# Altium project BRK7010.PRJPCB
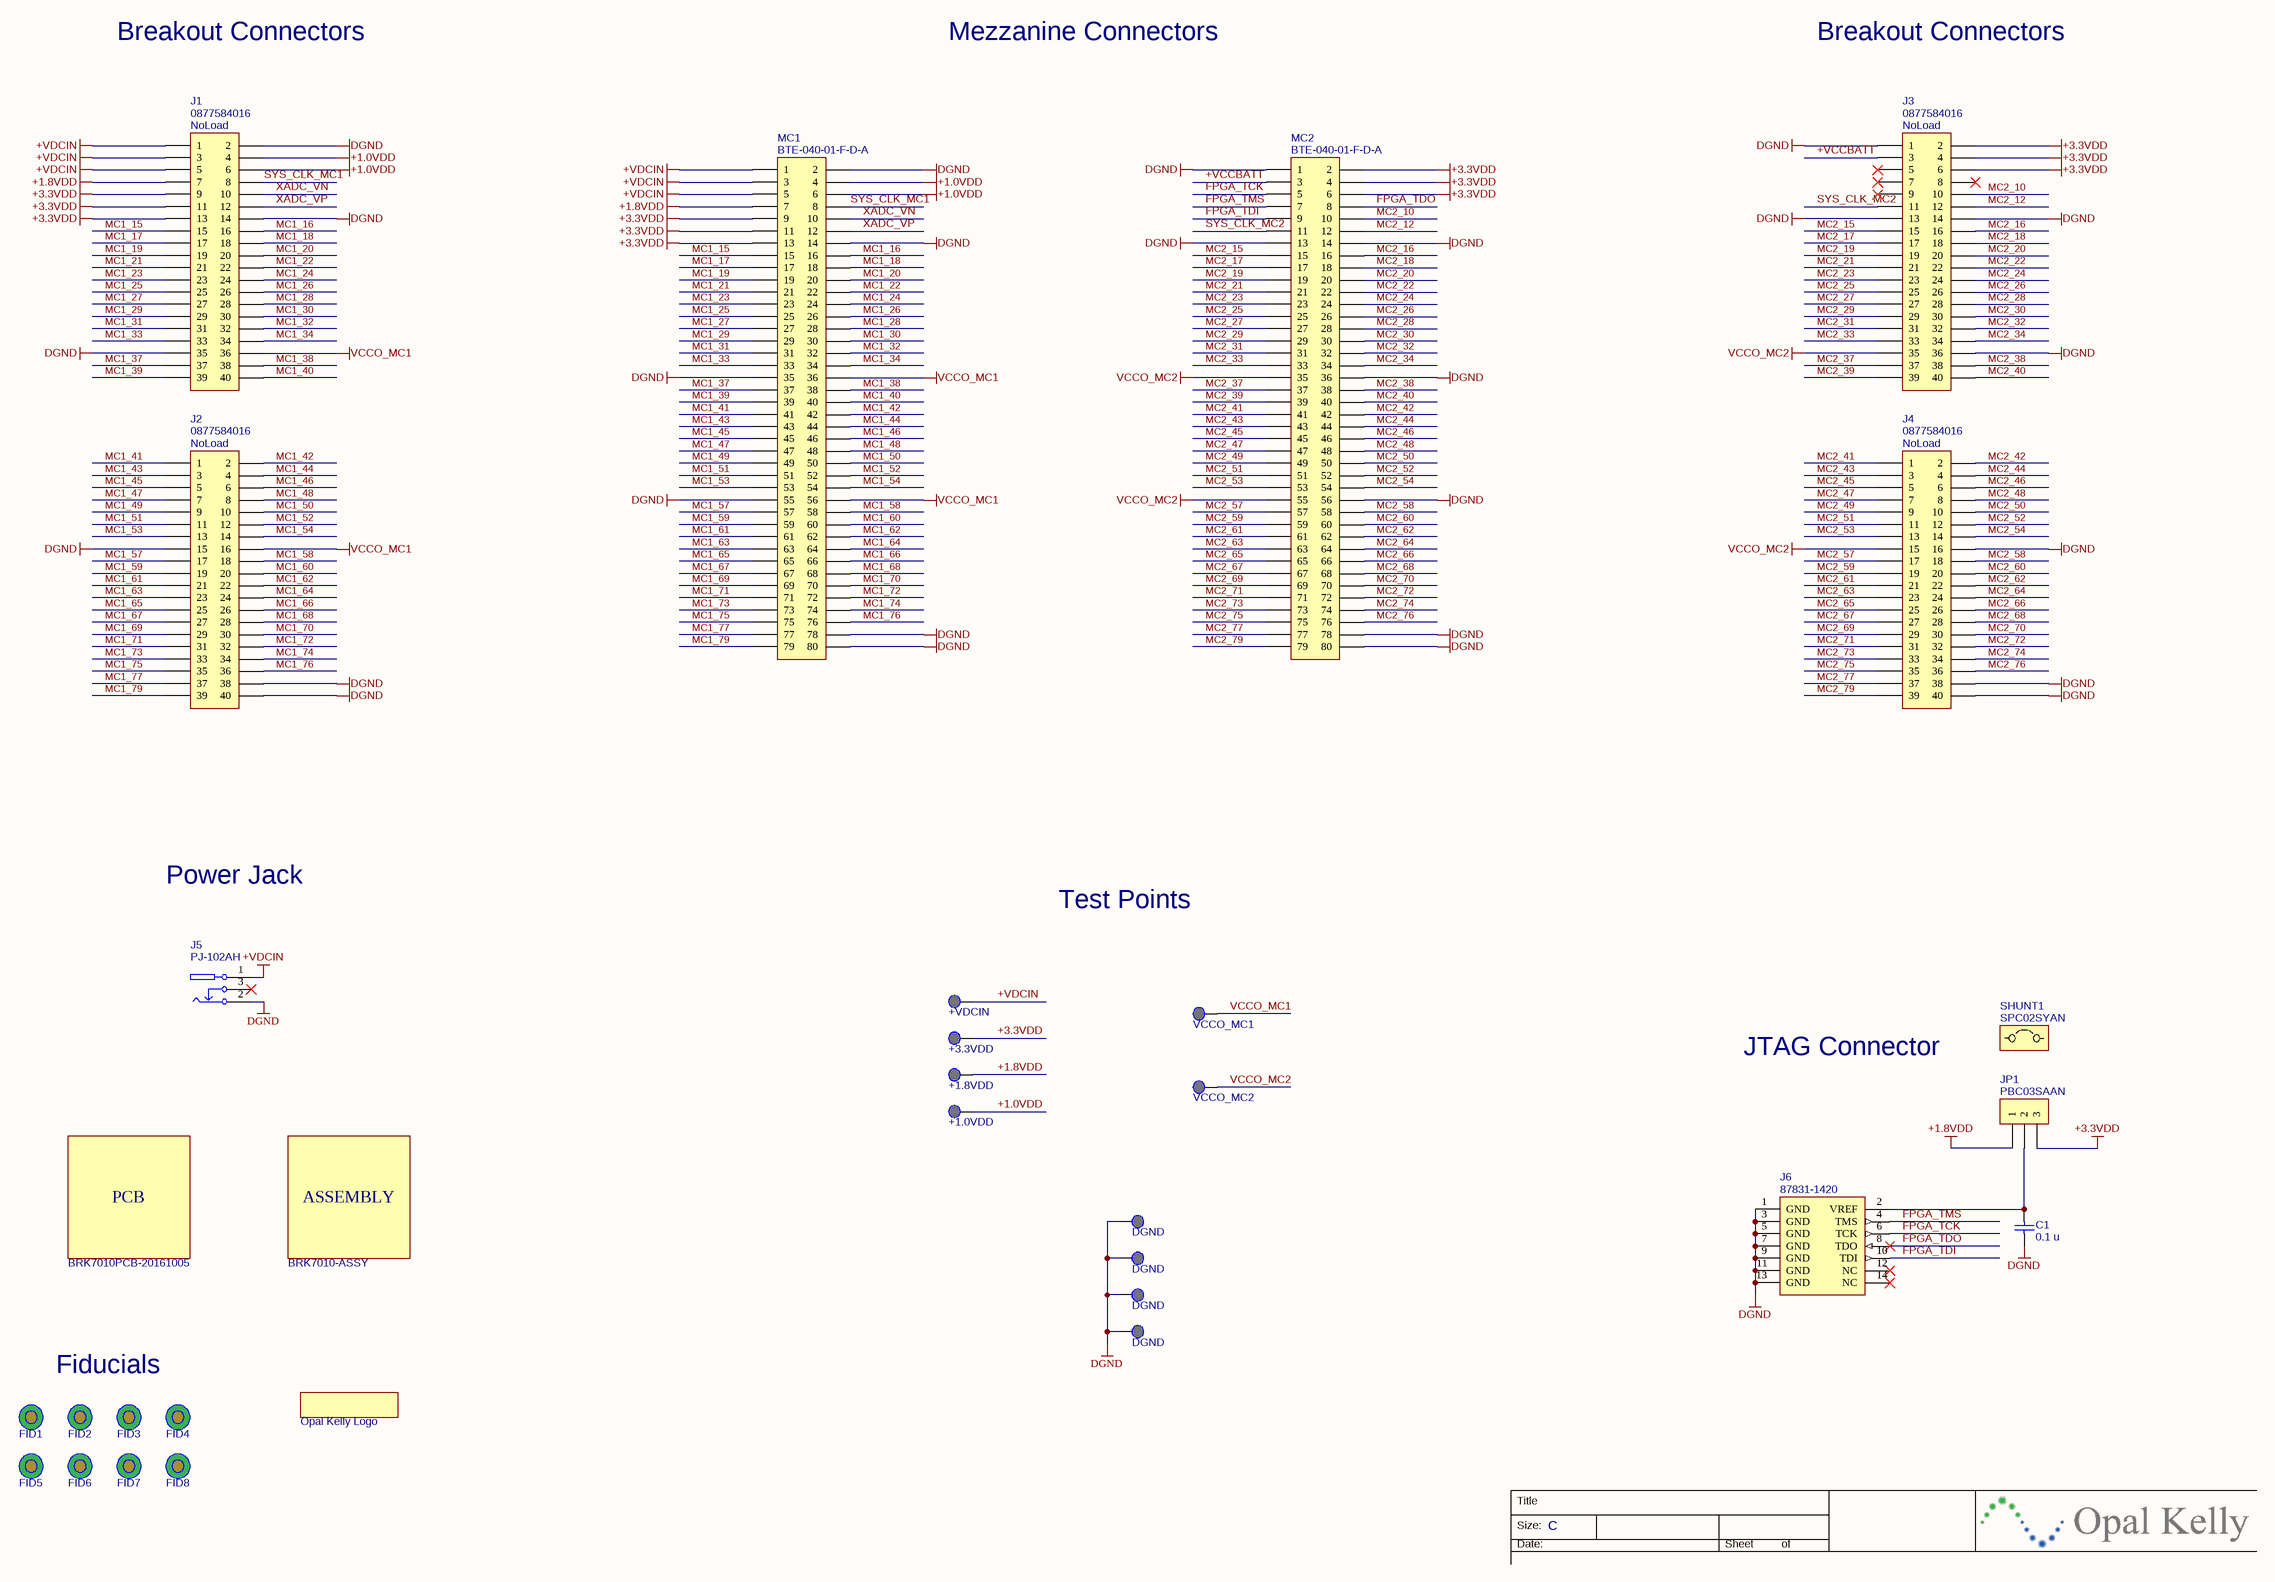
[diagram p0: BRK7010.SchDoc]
1 sheet, 32 parts. Net scope: global (net labels, ports and power ports of the same name join across sheets).
Board file: BRK7010.PcbDoc

## Sheet BRK7010.SchDoc: BRK7010
size C; Organization: Opal Kelly; Address1: 13500 SW 72nd Ave, STE 100; Address2: Portland, OR 97223; Address4: http://www.opalkelly.com; DocumentNumber: xxx; Revision: 1; SheetNumber: 1; SheetTotal: 1; PageSetup: Record=PageOptions¦CenterHorizontal=True¦CenterVertical=True¦PrintScale=0.54¦XCorrection=1.00¦YCorrection=1.00¦PrintKind=0¦BorderSize=5000000¦LeftOffset=0¦BottomOffset=0¦Orientation=2¦PaperLength=1000¦PaperWidth=1000¦Scale=100¦PaperSource=7¦PrintQuality=-4¦MediaType=1¦DitherType=10¦PaperKind=Letter¦PrintScaleMode=1

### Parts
*1  Opal Kelly Logo  [okLogo-23x5]
ASSY1  BRK7010-ASSY  (mechanical)
C1  value 0.1 u  [CAPC1608N]  (hidden comment: C0603C104K4RACTU)
FID1  FIDUCIAL  [FID1MM/2MM-SS]  (value not drawn)
FID2  FIDUCIAL  [FID1MM/2MM-SS]  (value not drawn)
FID3  FIDUCIAL  [FID1MM/2MM-SS]  (value not drawn)
FID4  FIDUCIAL  [FID1MM/2MM-SS]  (value not drawn)
FID5  FIDUCIAL  [FID1MM/2MM-SS]  (value not drawn)
FID6  FIDUCIAL  [FID1MM/2MM-SS]  (value not drawn)
FID7  FIDUCIAL  [FID1MM/2MM-SS]  (value not drawn)
FID8  FIDUCIAL  [FID1MM/2MM-SS]  (value not drawn)
J1  0877584016  [HDR2X20-2MM]
J2  0877584016  [HDR2X20-2MM]
J3  0877584016  [HDR2X20-2MM]
J4  0877584016  [HDR2X20-2MM]
J5  PJ-102AH  [CUI-PJ102A]
J6  87831-1420  [HDR2X7-2MM]
JP1  PBC03SAAN  [HDR1X3]
MC1  BTE-040-01-F-D-A  [BTE-040]
MC2  BTE-040-01-F-D-A  [BTE-040]
PCB1  BRK7010PCB-20161005  (mechanical)
SHUNT1  SPC02SYAN  (mechanical)
TP1  +VDCIN  [TP-PTH-65/100]
TP2  VCCO_MC1  [TP-PTH-65/100]
TP3  +3.3VDD  [TP-PTH-65/100]
TP4  +1.8VDD  [TP-PTH-65/100]
TP5  VCCO_MC2  [TP-PTH-65/100]
TP6  +1.0VDD  [TP-PTH-65/100]
TP7  DGND  [TP-PTH-65/100]
TP8  DGND  [TP-PTH-65/100]
TP9  DGND  [TP-PTH-65/100]
TP10  DGND  [TP-PTH-65/100]

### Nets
+1.0VDD: J1.4 J1.6 MC1.4 MC1.6 TP6.1(PIN)
+1.8VDD: J1.7 JP1.1 MC1.7 TP4.1(PIN)
+3.3VDD: J1.9 J1.11 J1.13 J3.2 J3.4 J3.6 JP1.3 MC1.9 MC1.11 MC1.13 MC2.2 MC2.4 MC2.6 TP3.1(PIN)
+VDCIN: J1.1 J1.3 J1.5 J5.1 MC1.1 MC1.3 MC1.5 TP1.1(PIN)
DGND: C1.1 J1.2 J1.14 J1.35 J2.15 J2.38 J2.40 J3.1 J3.13 J3.14 J3.36 J4.16 J4.38 J4.40 J5.2 J6.1(GND) J6.3(GND) J6.5(GND) J6.7(GND) J6.9(GND) J6.11(GND) J6.13(GND) MC1.2 MC1.14 MC1.35 MC1.55 MC1.78 MC1.80 MC2.1 MC2.13 MC2.14 MC2.36 MC2.56 MC2.78 MC2.80 TP7.1(PIN) TP8.1(PIN) TP9.1(PIN) TP10.1(PIN)
VCCO_MC1: J1.36 J2.16 MC1.36 MC1.56 TP2.1(PIN)
VCCO_MC2: J3.35 J4.15 MC2.35 MC2.55 TP5.1(PIN)
+VCCBATT: J3.3 MC2.3
FPGA_TCK: J6.6(TCK) MC2.5
FPGA_TDI: J6.10(TDI) MC2.9
FPGA_TDO: J6.8(TDO) MC2.8
FPGA_TMS: J6.4(TMS) MC2.7
MC1_15: J1.15 MC1.15
MC1_16: J1.16 MC1.16
MC1_17: J1.17 MC1.17
MC1_18: J1.18 MC1.18
MC1_19: J1.19 MC1.19
MC1_20: J1.20 MC1.20
MC1_21: J1.21 MC1.21
MC1_22: J1.22 MC1.22
MC1_23: J1.23 MC1.23
MC1_24: J1.24 MC1.24
MC1_25: J1.25 MC1.25
MC1_26: J1.26 MC1.26
MC1_27: J1.27 MC1.27
MC1_28: J1.28 MC1.28
MC1_29: J1.29 MC1.29
MC1_30: J1.30 MC1.30
MC1_31: J1.31 MC1.31
MC1_32: J1.32 MC1.32
MC1_33: J1.33 MC1.33
MC1_34: J1.34 MC1.34
MC1_37: J1.37 MC1.37
MC1_38: J1.38 MC1.38
MC1_39: J1.39 MC1.39
MC1_40: J1.40 MC1.40
MC1_41: J2.1 MC1.41
MC1_42: J2.2 MC1.42
MC1_43: J2.3 MC1.43
MC1_44: J2.4 MC1.44
MC1_45: J2.5 MC1.45
MC1_46: J2.6 MC1.46
MC1_47: J2.7 MC1.47
MC1_48: J2.8 MC1.48
MC1_49: J2.9 MC1.49
MC1_50: J2.10 MC1.50
MC1_51: J2.11 MC1.51
MC1_52: J2.12 MC1.52
MC1_53: J2.13 MC1.53
MC1_54: J2.14 MC1.54
MC1_57: J2.17 MC1.57
MC1_58: J2.18 MC1.58
MC1_59: J2.19 MC1.59
MC1_60: J2.20 MC1.60
MC1_61: J2.21 MC1.61
MC1_62: J2.22 MC1.62
MC1_63: J2.23 MC1.63
MC1_64: J2.24 MC1.64
MC1_65: J2.25 MC1.65
MC1_66: J2.26 MC1.66
MC1_67: J2.27 MC1.67
MC1_68: J2.28 MC1.68
MC1_69: J2.29 MC1.69
MC1_70: J2.30 MC1.70
MC1_71: J2.31 MC1.71
MC1_72: J2.32 MC1.72
MC1_73: J2.33 MC1.73
MC1_74: J2.34 MC1.74
MC1_75: J2.35 MC1.75
MC1_76: J2.36 MC1.76
MC1_77: J2.37 MC1.77
MC1_79: J2.39 MC1.79
MC2_10: J3.10 MC2.10
MC2_12: J3.12 MC2.12
MC2_15: J3.15 MC2.15
MC2_16: J3.16 MC2.16
MC2_17: J3.17 MC2.17
MC2_18: J3.18 MC2.18
MC2_19: J3.19 MC2.19
MC2_20: J3.20 MC2.20
MC2_21: J3.21 MC2.21
MC2_22: J3.22 MC2.22
MC2_23: J3.23 MC2.23
MC2_24: J3.24 MC2.24
MC2_25: J3.25 MC2.25
MC2_26: J3.26 MC2.26
MC2_27: J3.27 MC2.27
MC2_28: J3.28 MC2.28
MC2_29: J3.29 MC2.29
MC2_30: J3.30 MC2.30
MC2_31: J3.31 MC2.31
MC2_32: J3.32 MC2.32
MC2_33: J3.33 MC2.33
MC2_34: J3.34 MC2.34
MC2_37: J3.37 MC2.37
MC2_38: J3.38 MC2.38
MC2_39: J3.39 MC2.39
MC2_40: J3.40 MC2.40
MC2_41: J4.1 MC2.41
MC2_42: J4.2 MC2.42
MC2_43: J4.3 MC2.43
MC2_44: J4.4 MC2.44
MC2_45: J4.5 MC2.45
MC2_46: J4.6 MC2.46
MC2_47: J4.7 MC2.47
MC2_48: J4.8 MC2.48
MC2_49: J4.9 MC2.49
MC2_50: J4.10 MC2.50
MC2_51: J4.11 MC2.51
MC2_52: J4.12 MC2.52
MC2_53: J4.13 MC2.53
MC2_54: J4.14 MC2.54
MC2_57: J4.17 MC2.57
MC2_58: J4.18 MC2.58
MC2_59: J4.19 MC2.59
MC2_60: J4.20 MC2.60
MC2_61: J4.21 MC2.61
MC2_62: J4.22 MC2.62
MC2_63: J4.23 MC2.63
MC2_64: J4.24 MC2.64
MC2_65: J4.25 MC2.65
MC2_66: J4.26 MC2.66
MC2_67: J4.27 MC2.67
MC2_68: J4.28 MC2.68
MC2_69: J4.29 MC2.69
MC2_70: J4.30 MC2.70
MC2_71: J4.31 MC2.71
MC2_72: J4.32 MC2.72
MC2_73: J4.33 MC2.73
MC2_74: J4.34 MC2.74
MC2_75: J4.35 MC2.75
MC2_76: J4.36 MC2.76
MC2_77: J4.37 MC2.77
MC2_79: J4.39 MC2.79
SYS_CLK_MC1: J1.8 MC1.8
SYS_CLK_MC2: J3.11 MC2.11
XADC_VN: J1.10 MC1.10
XADC_VP: J1.12 MC1.12
NetC1_2: C1.2 J6.2(VREF) JP1.2

Not connected (* = marked no-connect by the designer): J3 5* 7* 8* 9*; J5 3*; J6 12(NC)* 14(NC)*

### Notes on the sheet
- Breakout Connectors
- Mezzanine Connectors
- Power Jack
- Test Points
- JTAG Connector
- Fiducials
- Title
- Size:
- Date:
- C
- Sheet
- of

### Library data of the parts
*1 = OKLOGO
ASSY1 = 001451: BRK7010 PCB assembly; Manufacturer: PCB Assembly Cost; partnumber: 001451
C1 = 000019: Ceramic capacitor; Manufacturer: Kemet; partnumber: 000019; Description 2: SM-0603, 10%, 16v, X7R; ValueFloat: 1E-7
FID1-FID8 = FIDUCIAL: PCB fiducial
J1-J4 = 000583: 2mm header, 20x2, thru-hole; Manufacturer: Molex; partnumber: 000583
J5 = 000356: DC power connector - high current; Manufacturer: CUI Inc.; partnumber: 000356; Description 2: 2.1mm / 5.5mm
J6 = 000541: 2mm header, shrouded; Manufacturer: Molex; partnumber: 000541; Description 2: Dual-row, 14-pos, Xilinx JTAG compatible
JP1 = 001173: Single-row header; Manufacturer: Sullins Electronics Corp.; partnumber: 001173; Description 2: Male, 0.1", 3-pos
MC1 MC2 = 000059: 0.8mm high-density header; Manufacturer: Samtec; partnumber: 000059; Description 2: 80-pin, Gold flash, Mated height: 5.00mm (0.197 inch)
PCB1 = 001452: PCB for BRK7010; Manufacturer: Generic PCB Manufacturer; partnumber: 001452; x_lifecycle_status: Prototype
SHUNT1 = 000078: 0.1" shunt; Manufacturer: Sullins Electronics Corp.; partnumber: 000078; Description 2: Gold flash finish; x_lifecycle_status: Production
TP1-TP10 = TP-PTH-65/100: Test point, plated through-hole, 65/100mil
